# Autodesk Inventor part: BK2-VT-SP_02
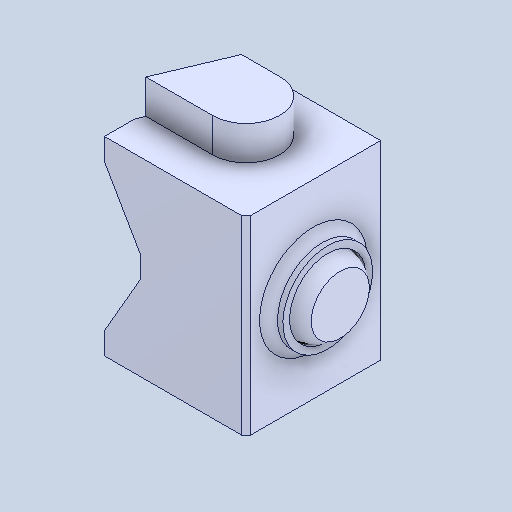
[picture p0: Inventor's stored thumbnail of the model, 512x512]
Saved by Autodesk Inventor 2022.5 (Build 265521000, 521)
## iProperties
Created: 2024-08
Part Number: BK2-VT-SP_02
Material: 一般
Document SubType Name: Modeling
Designer: ImaoCorp
Density: 1 g/cm^3
Appearance: 既定
Author: ImaoCorp
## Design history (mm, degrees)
feature "BK2-VT-SP_02"
node "ソリッド1"
